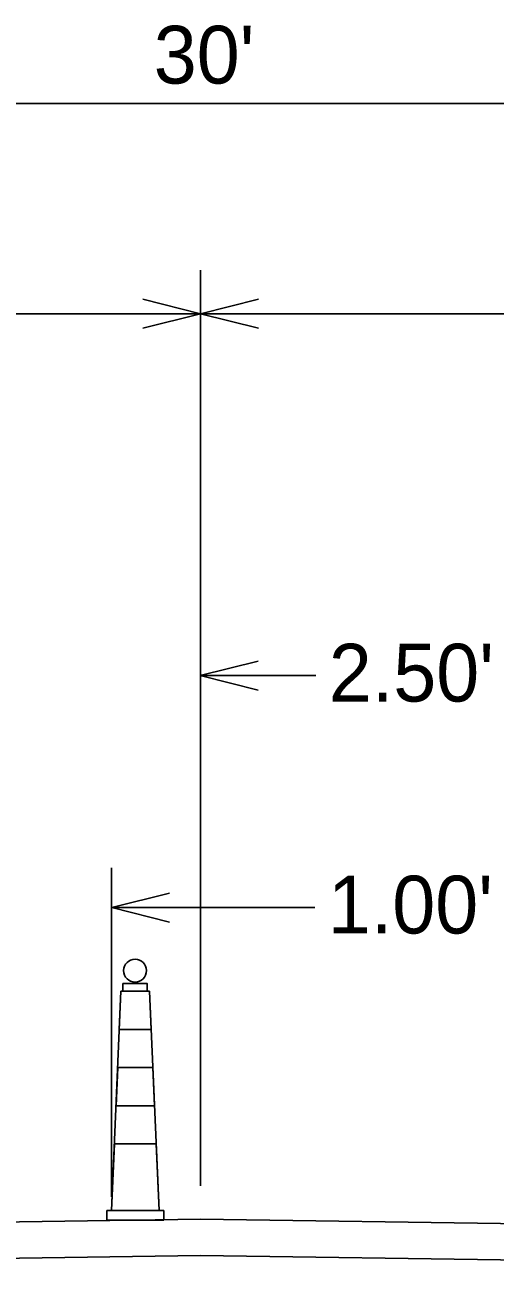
# Model space of a CAD drawing. Extents: x 10133 to 81668, y 4692 to 11018.
# Drawn here: x 11631 to 11815.7, y 8388.1 to 8878.4 of the extents above; entities that cross this region are included whole.
import ezdxf

# ---------------------------------------------------------------- set-up
doc = ezdxf.new("R2010")
doc.units = 0
doc.layers.add('Level 7', color=7, linetype='Continuous')
doc.layers.add('Stage_Construction Traffic Control', color=7, linetype='Continuous')

msp = doc.modelspace()

# ---------------------------------------------------------------- linework, layer by layer
at = {"layer": 'Level 7'}
for p, q in [((11295.03, 8847.53), (12105.03, 8847.53)), ((11700.03, 8421.95), (11700.03, 8782.01)), ((11700.03, 8764.82), (11677.32, 8770.5)), ((11722.74, 8770.5), (11700.03, 8764.82)), ((11700.03, 8764.82), (11295.03, 8764.82)), ((11677.32, 8759.14), (11700.03, 8764.82)), ((12105.03, 8764.82), (11700.03, 8764.82)), ((11700.03, 8764.82), (11722.74, 8759.14)), ((11745.33, 8622.54), (11699.91, 8622.54)), ((11664.98, 8417.62), (11664.98, 8547.05)), ((11744.95, 8531.36), (11665.1, 8531.36)), ((11264.61, 8402.34), (11700.03, 8408.87)), ((12135.44, 8402.34), (11700.03, 8408.87)), ((11264.61, 8388.06), (11700.03, 8394.59)), ((12135.44, 8388.06), (11700.03, 8394.59))]:
    msp.add_line(p, q, dxfattribs=at)
for points in [[(11722.62, 8628.22), (11699.91, 8622.54), (11722.62, 8616.87)], [(11687.81, 8537.04), (11665.1, 8531.36), (11687.81, 8525.69)]]:
    msp.add_lwpolyline(points, dxfattribs=at)
at = {"layer": 'Stage_Construction Traffic Control'}
for p, q in [((11668.73, 8498.48), (11664.98, 8412.23)), ((11668.73, 8498.48), (11668.08, 8483.48)), ((11679.98, 8498.48), (11668.73, 8498.48)), ((11679.98, 8498.48), (11668.73, 8498.48)), ((11683.73, 8412.23), (11679.98, 8498.48)), ((11680.64, 8483.48), (11679.98, 8498.48)), ((11680.64, 8483.48), (11668.08, 8483.48)), ((11668.08, 8483.48), (11680.64, 8483.48)), ((11667.43, 8468.48), (11666.78, 8453.48)), ((11681.29, 8468.48), (11667.43, 8468.48)), ((11681.29, 8468.48), (11667.43, 8468.48)), ((11681.94, 8453.48), (11681.29, 8468.48)), ((11681.94, 8453.48), (11666.78, 8453.48)), ((11666.78, 8453.48), (11681.94, 8453.48)), ((11666.13, 8438.48), (11664.98, 8412.23)), ((11682.59, 8438.48), (11666.13, 8438.48)), ((11682.59, 8438.48), (11666.13, 8438.48)), ((11683.73, 8412.23), (11682.59, 8438.48)), ((11685.61, 8412.23), (11663.11, 8412.23)), ((11663.11, 8412.23), (11663.11, 8408.48)), ((11664.98, 8412.23), (11683.73, 8412.23)), ((11685.61, 8408.48), (11685.61, 8412.23)), ((11685.61, 8408.48), (11663.11, 8408.48))]:
    msp.add_line(p, q, dxfattribs=at)
msp.add_lwpolyline([(11669.48, 8501.48), (11679.08, 8501.48), (11679.08, 8498.48), (11669.48, 8498.48)], close=True, dxfattribs=at)
msp.add_circle((11674.28, 8506.58), 4.5, dxfattribs=at)

# ---------------------------------------------------------------- texts
at = {"layer": 'Level 7'}
for s, p in [("30'", (11681.61, 8855.33)), ("2.50'", (11750.42, 8612.36)), ("1.00'", (11750.03, 8521.18))]:
    msp.add_text(s, height=22.709, dxfattribs=at).set_placement(p)

doc.saveas('drawing.dxf')
